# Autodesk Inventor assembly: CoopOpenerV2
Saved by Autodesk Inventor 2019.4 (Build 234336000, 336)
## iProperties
Created: 2020-02
Part Number: CoopOpenerV2
Document SubType Name: Assembly
Designer: Administrator
Title: CoopOpenerV2 v124
Author: Administrator
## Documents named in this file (13)
- c:\worker\convert-fusion-r01\tmp\job-1\260\output\files\1843549f-c54a-4787-9036-05e5cb857b53\28a9f49f-c78d-4f26-968f-a4f11d6073cc.iam
- c:\worker\convert-fusion-r01\tmp\job-1\260\output\files\1843549f-c54a-4787-9036-05e5cb857b53\lid.ipt
- c:\worker\convert-fusion-r01\tmp\job-1\260\output\files\1843549f-c54a-4787-9036-05e5cb857b53\PulleyHolder.ipt
- c:\worker\convert-fusion-r01\tmp\job-1\260\output\files\1843549f-c54a-4787-9036-05e5cb857b53\Component3.ipt
- c:\worker\convert-fusion-r01\tmp\job-1\260\output\files\1843549f-c54a-4787-9036-05e5cb857b53\Component4.ipt
- c:\worker\convert-fusion-r01\tmp\job-1\260\output\files\1843549f-c54a-4787-9036-05e5cb857b53\Component5.ipt
- c:\worker\convert-fusion-r01\tmp\job-1\260\output\files\1843549f-c54a-4787-9036-05e5cb857b53\Component6.ipt
- c:\worker\convert-fusion-r01\tmp\job-1\260\output\files\1843549f-c54a-4787-9036-05e5cb857b53\Component7.ipt
- c:\worker\convert-fusion-r01\tmp\job-1\260\output\files\1843549f-c54a-4787-9036-05e5cb857b53\Spur Gear (12 teeth).ipt
- c:\worker\convert-fusion-r01\tmp\job-1\260\output\files\1843549f-c54a-4787-9036-05e5cb857b53\Spur Gear (24 teeth).ipt
- c:\worker\convert-fusion-r01\tmp\job-1\260\output\files\1843549f-c54a-4787-9036-05e5cb857b53\Spur Gear (24 teeth) (1).ipt
- c:\worker\convert-fusion-r01\tmp\job-1\260\output\files\1843549f-c54a-4787-9036-05e5cb857b53\Spur Gear (24 teeth) (2).ipt
- c:\worker\convert-fusion-r01\tmp\job-1\260\output\files\1843549f-c54a-4787-9036-05e5cb857b53\CoopOpenerV2 v124.ipt
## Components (12 placed, 12 different names)
1. lid:1
2. PulleyHolder:1
3. Component3:1
4. Component4:1
5. Component5:1
6. Component6:1
7. Component7:1
8. Spur Gear (12 teeth):1
9. Spur Gear (24 teeth):1
10. Spur Gear (24 teeth) (1):1
11. Spur Gear (24 teeth) (2):1
12. CoopOpenerV2 v124
